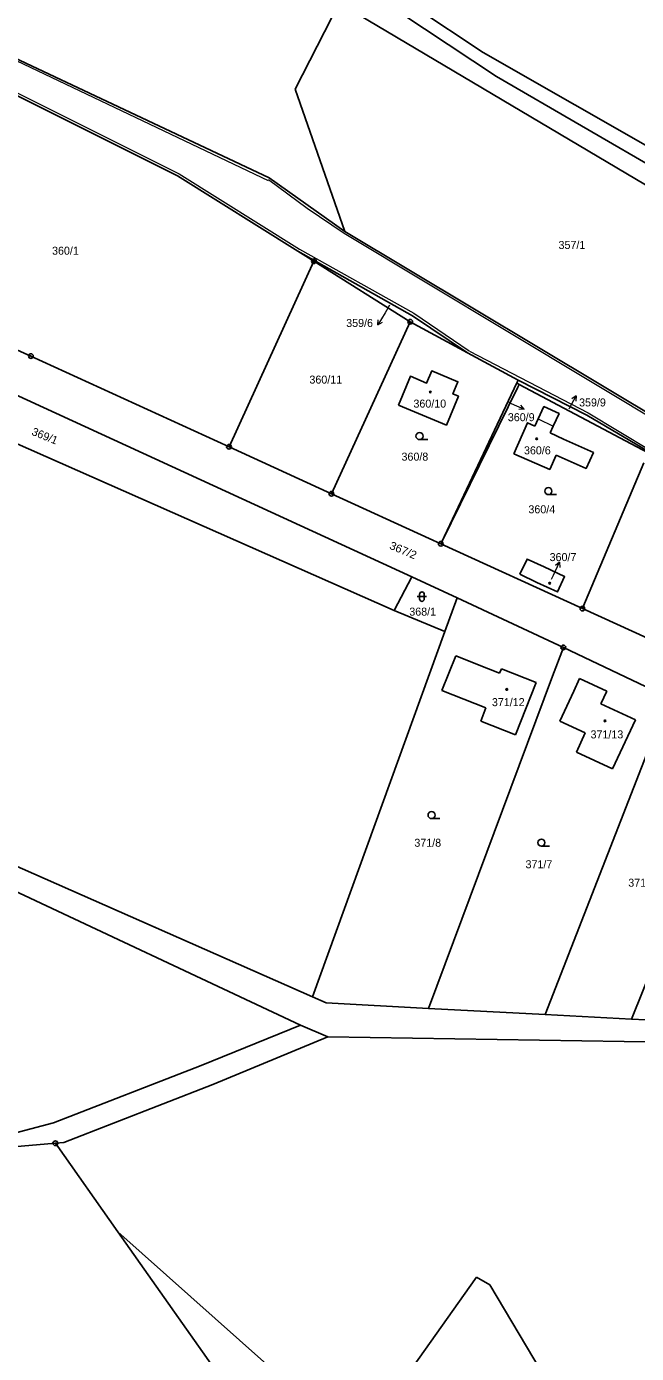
# Model space of a CAD drawing. Extents: x -633485 to -630509, y -1112692 to -1108818.
# Drawn here: x -632393.4 to -632263.7, y -1111932.7 to -1111650.8 of the extents above; entities that cross this region are included whole.
import ezdxf
from ezdxf.enums import TextEntityAlignment as Align

# ---------------------------------------------------------------- set-up
doc = ezdxf.new("R2010")
doc.units = 0
doc.header["$LTSCALE"] = 0.68
for name, color, linetype, lineweight in [('1', 7, 'Continuous', 25), ('3', 7, 'Continuous', 25), ('4', 7, 'Continuous', 13), ('5', 7, 'Continuous', 25), ('7', 7, 'Continuous', 13), ('8', 7, 'Continuous', 25)]:
    doc.layers.add(name, color=color, linetype=linetype, lineweight=lineweight)
doc.layers.add('2', color=7, linetype='Continuous')

msp = doc.modelspace()

# ---------------------------------------------------------------- linework, layer by layer
at = {"layer": '1'}
for p, q in [((-632321.48, -1111642.92), (-632293.52, -1111661.47)), ((-632336.28, -1111664.14), (-632326.93, -1111645.87)), ((-632326.93, -1111645.87), (-632261.86, -1111684.44)), ((-632310.86, -1111646.71), (-632296.31, -1111656.36)), ((-632401.29, -1111654.98), (-632341.82, -1111682.99)), ((-632296.31, -1111656.36), (-632257.3, -1111678.64)), ((-632403.76, -1111661.33), (-632361.26, -1111682.53)), ((-632336.28, -1111664.14), (-632325.73, -1111694.38)), ((-632293.52, -1111661.47), (-632245.01, -1111689.64)), ((-632475.12, -1111683.9), (-632392.43, -1111720.84)), ((-632361.26, -1111682.53), (-632335.74, -1111698.55)), ((-632341.82, -1111682.99), (-632325.73, -1111694.38)), ((-632325.73, -1111694.38), (-632220.93, -1111757.12)), ((-632483.69, -1111700.54), (-632315.26, -1111774.87)), ((-632350.34, -1111740.12), (-632332.3, -1111700.71)), ((-632335.74, -1111698.55), (-632311.37, -1111712.28)), ((-632335.74, -1111698.55), (-632332.3, -1111700.71)), ((-632332.3, -1111700.71), (-632311.84, -1111713.55)), ((-632328.57, -1111750.09), (-632311.84, -1111713.55)), ((-632311.84, -1111713.55), (-632299.65, -1111720.15)), ((-632311.37, -1111712.28), (-632299.65, -1111720.15)), ((-632299.65, -1111720.15), (-632288.91, -1111725.97)), ((-632392.43, -1111720.84), (-632350.34, -1111740.12)), ((-632289.18, -1111726.54), (-632288.91, -1111725.97)), ((-632288.91, -1111725.97), (-632274.31, -1111733.41)), ((-632395.9, -1111728.92), (-632311.46, -1111767.74)), ((-632305.21, -1111760.47), (-632289.18, -1111726.54)), ((-632305.21, -1111760.47), (-632288.94, -1111727.46)), ((-632289.18, -1111726.54), (-632288.65, -1111726.87)), ((-632288.94, -1111727.46), (-632288.65, -1111726.87)), ((-632288.65, -1111726.87), (-632261.27, -1111741.38)), ((-632284.65, -1111734.2), (-632285.36, -1111735.72)), ((-632274.31, -1111733.41), (-632261.17, -1111741.15)), ((-632282.12, -1111737.18), (-632281.44, -1111735.71)), ((-632279.22, -1111738.49), (-632282.12, -1111737.18)), ((-632350.34, -1111740.12), (-632328.57, -1111750.09)), ((-632275.15, -1111774.29), (-632262.16, -1111743.5)), ((-632328.57, -1111750.09), (-632307.83, -1111759.59)), ((-632307.83, -1111759.59), (-632305.34, -1111760.73)), ((-632305.34, -1111760.73), (-632305.21, -1111760.47)), ((-632305.34, -1111760.73), (-632275.23, -1111774.49)), ((-632315.26, -1111774.87), (-632311.46, -1111767.74)), ((-632311.46, -1111767.74), (-632301.87, -1111772.21)), ((-632284.91, -1111768.92), (-632288.53, -1111767.18)), ((-632304.46, -1111779.34), (-632301.87, -1111772.21)), ((-632301.87, -1111772.21), (-632279.29, -1111782.74)), ((-632315.26, -1111774.87), (-632304.46, -1111779.34)), ((-632275.23, -1111774.49), (-632275.15, -1111774.29)), ((-632275.23, -1111774.49), (-632252.52, -1111784.87)), ((-632332.59, -1111857), (-632304.46, -1111779.34)), ((-632305.08, -1111791.92), (-632302.14, -1111784.5)), ((-632302.14, -1111784.5), (-632295.17, -1111787.28)), ((-632281.56, -1111788.82), (-632279.29, -1111782.74)), ((-632279.29, -1111782.74), (-632256.84, -1111793.46)), ((-632295.17, -1111787.28), (-632292.84, -1111788.2)), ((-632292.84, -1111788.2), (-632292.44, -1111787.26)), ((-632292.44, -1111787.26), (-632285.03, -1111790.16)), ((-632307.96, -1111859.42), (-632281.56, -1111788.82)), ((-632289.48, -1111801.32), (-632285.03, -1111790.16)), ((-632277.09, -1111792.06), (-632275.83, -1111789.31)), ((-632275.83, -1111789.31), (-632270.06, -1111792.02)), ((-632305.08, -1111791.92), (-632298.1, -1111794.67)), ((-632280.05, -1111798.38), (-632277.09, -1111792.06)), ((-632271.3, -1111794.73), (-632270.06, -1111792.02)), ((-632298.1, -1111794.67), (-632295.79, -1111795.58)), ((-632296.85, -1111798.39), (-632295.79, -1111795.58)), ((-632271.3, -1111794.73), (-632263.98, -1111798.12)), ((-632296.85, -1111798.39), (-632289.48, -1111801.32)), ((-632283.16, -1111860.74), (-632258.76, -1111798.26)), ((-632280.05, -1111798.38), (-632274.62, -1111800.9)), ((-632268.82, -1111808.56), (-632263.98, -1111798.12)), ((-632276.51, -1111804.98), (-632274.62, -1111800.9)), ((-632276.51, -1111804.98), (-632268.82, -1111808.56)), ((-632264.78, -1111861.71), (-632242.18, -1111805.12)), ((-632407.97, -1111823.75), (-632332.59, -1111857)), ((-632409.47, -1111828.13), (-632335.16, -1111862.99)), ((-632332.59, -1111857), (-632329.72, -1111858.27)), ((-632329.72, -1111858.27), (-632307.96, -1111859.42)), ((-632307.96, -1111859.42), (-632283.16, -1111860.74)), ((-632283.16, -1111860.74), (-632264.78, -1111861.71)), ((-632356.26, -1111871.52), (-632335.16, -1111862.99)), ((-632335.16, -1111862.99), (-632329.36, -1111865.46)), ((-632264.78, -1111861.71), (-632261.78, -1111861.87)), ((-632353.81, -1111875.59), (-632329.36, -1111865.46)), ((-632329.36, -1111865.46), (-632244.47, -1111866.78)), ((-632387.64, -1111883.74), (-632356.26, -1111871.52)), ((-632385.42, -1111887.9), (-632353.81, -1111875.59)), ((-632490.92, -1111910.84), (-632387.64, -1111883.74)), ((-632399.48, -1111889.14), (-632387.25, -1111888.06)), ((-632373.97, -1111906.88), (-632301.86, -1112009.08)), ((-632373.97, -1111906.88), (-632321.63, -1111953.4)), ((-632316.23, -1111942.57), (-632297.75, -1111916.51)), ((-632297.75, -1111916.51), (-632294.94, -1111918.17)), ((-632294.94, -1111918.17), (-632280.07, -1111943.06))]:
    msp.add_line(p, q, dxfattribs=at)
msp.add_lwpolyline([(-632314.32, -1111731.25), (-632311.79, -1111725.15), (-632308.35, -1111726.57), (-632307.27, -1111723.99), (-632301.68, -1111726.3), (-632302.74, -1111728.9), (-632301.6, -1111729.37), (-632304.14, -1111735.5)], close=True, dxfattribs=at)
for points in [[(-632281.44, -1111735.71), (-632280.21, -1111733.07), (-632283.43, -1111731.57), (-632284.65, -1111734.2)], [(-632285.36, -1111735.72), (-632286.89, -1111735.03), (-632289.78, -1111741.59)], [(-632280.78, -1111741.88), (-632274.45, -1111744.73), (-632272.91, -1111741.34), (-632279.22, -1111738.49)], [(-632289.78, -1111741.59), (-632282.16, -1111744.92), (-632280.78, -1111741.88)], [(-632288.53, -1111767.18), (-632286.99, -1111763.97), (-632283.38, -1111765.63)], [(-632283.38, -1111765.63), (-632279.03, -1111767.68), (-632280.52, -1111770.96), (-632284.91, -1111768.92)], [(-632373.97, -1111906.88), (-632387.25, -1111888.06), (-632385.42, -1111887.9)]]:
    msp.add_lwpolyline(points, dxfattribs=at)
at = {"layer": '3'}
for p, q in [((-632309.853, -1111738.6), (-632308.103, -1111738.6)), ((-632282.463, -1111750.28), (-632280.713, -1111750.28)), ((-632310.341, -1111771.951), (-632308.339, -1111771.951)), ((-632309.841, -1111771.451), (-632309.841, -1111772.452)), ((-632308.839, -1111772.452), (-632308.839, -1111771.451)), ((-632307.293, -1111819.11), (-632305.543, -1111819.11)), ((-632283.953, -1111824.96), (-632282.203, -1111824.96))]:
    msp.add_line(p, q, dxfattribs=at)
for centre in [(-632309.8529, -1111737.8498), (-632282.4629, -1111749.5298), (-632307.2929, -1111818.3598), (-632283.9529, -1111824.2098)]:
    msp.add_circle(centre, 0.75, dxfattribs=at)
for centre, start, end in [((-632309.34, -1111771.4509), 0, 180), ((-632309.34, -1111772.4509), 180, 359.98789)]:
    msp.add_arc(centre, 0.5, start, end, dxfattribs=at)
at = {"layer": '4'}
msp.add_line((-632284.65, -1111734.2), (-632281.44, -1111735.71), dxfattribs=at)
for points in [[(-632913.37, -1111284.14), (-632903.43, -1111296.53), (-632901.68, -1111300.19), (-632898.25, -1111304.55), (-632839.91, -1111353.26), (-632811.33, -1111379.91), (-632794.53, -1111397.53), (-632770.8, -1111417.89), (-632733.49, -1111454.85), (-632690.42, -1111489.51), (-632643.95, -1111526.86), (-632609.47, -1111548.69), (-632587.98, -1111560.83), (-632517.06, -1111600.62), (-632481.03, -1111616.96), (-632456.42, -1111631), (-632403.52, -1111660.86), (-632360.95, -1111682.17), (-632335.39, -1111698.14), (-632311.04, -1111711.72), (-632299.3, -1111719.74)], [(-632341.95, -1111683.59), (-632401.36, -1111655.37), (-632476.91, -1111613.68), (-632582.67, -1111558.34), (-632600.05, -1111546.02), (-632611.42, -1111539.57), (-632654.27, -1111513.39), (-632683.89, -1111486.15), (-632729.95, -1111449.04), (-632752.07, -1111426.79), (-632756.78, -1111422.08), (-632808.8, -1111374.42), (-632836.64, -1111350.53)], [(-632121.32, -1111799.36), (-632153.88, -1111790.41), (-632209.17, -1111764.74), (-632221.14, -1111757.71), (-632325.85, -1111694.81), (-632333.76, -1111689.52), (-632341.95, -1111683.42)], [(-632299.24, -1111719.8), (-632274.04, -1111732.92), (-632260.85, -1111740.83), (-632218.48, -1111766.08), (-632218.07, -1111765.09), (-632212.08, -1111768.29), (-632212.31, -1111769.16), (-632189.88, -1111779.63)]]:
    msp.add_lwpolyline(points, dxfattribs=at)
at = {"layer": '5'}
for centre in [(-632307.5468, -1111728.4892), (-632284.9668, -1111738.4292), (-632282.1968, -1111769.0992), (-632291.3068, -1111791.6692), (-632270.4268, -1111798.3392)]:
    msp.add_circle(centre, 0.175, dxfattribs=at)
at = {"layer": '7'}
for p, q in [((-632318.68, -1111714.239), (-632317.746, -1111713.622)), ((-632287.64, -1111732.158), (-632288.336, -1111731.281)), ((-632276.555, -1111729.325), (-632277.479, -1111729.958)), ((-632280.074, -1111764.663), (-632280.964, -1111765.343))]:
    msp.add_line(p, q, dxfattribs=at)
for points in [[(-632316.24, -1111710), (-632317.18, -1111711.64), (-632318.68, -1111714.239), (-632318.613, -1111713.121)], [(-632290.85, -1111730.67), (-632290.36, -1111730.89), (-632287.64, -1111732.158), (-632288.759, -1111732.189)], [(-632278.07, -1111732.06), (-632278.01, -1111731.95), (-632276.555, -1111729.325), (-632276.603, -1111730.444)], [(-632281.82, -1111768.26), (-632281.39, -1111767.36), (-632280.074, -1111764.663), (-632280.063, -1111765.782)]]:
    msp.add_lwpolyline(points, dxfattribs=at)
at = {"layer": '8'}
for centre, radius in [((-632332.3, -1111700.7099), 0.5), ((-632332.3, -1111700.7099), 0.0303), ((-632311.84, -1111713.5499), 0.5), ((-632311.84, -1111713.5499), 0.0303), ((-632392.43, -1111720.8399), 0.5), ((-632392.43, -1111720.8399), 0.0303), ((-632350.34, -1111740.1199), 0.5), ((-632350.34, -1111740.1199), 0.0303), ((-632328.57, -1111750.0899), 0.5), ((-632328.57, -1111750.0899), 0.0303), ((-632305.34, -1111760.7299), 0.5), ((-632305.34, -1111760.7299), 0.0303), ((-632275.23, -1111774.4899), 0.5), ((-632275.23, -1111774.4899), 0.0303), ((-632279.29, -1111782.7399), 0.5), ((-632279.29, -1111782.7399), 0.0303), ((-632387.25, -1111888.0599), 0.5), ((-632387.25, -1111888.0599), 0.0303)]:
    msp.add_circle(centre, radius, dxfattribs=at)

# ---------------------------------------------------------------- texts
at = {"layer": '2'}
for s, p in [('360/1', (-632387.95, -1111699.315)), ('357/1', (-632280.31, -1111698.095)), ('360/11', (-632333.25, -1111726.695)), ('360/8', (-632313.68, -1111743.065)), ('360/4', (-632286.71, -1111754.245)), ('368/1', (-632312.03, -1111775.985)), ('371/12', (-632294.47, -1111795.215)), ('371/13', (-632273.51, -1111802.065)), ('371/8', (-632310.95, -1111825.085)), ('371/7', (-632287.32, -1111829.655)), ('371/6', (-632265.49, -1111833.575))]:
    msp.add_text(s, height=1.7, dxfattribs=at).set_placement(p)
for s, p in [('359/6', (-632322.59, -1111714.665)), ('360/10', (-632307.67, -1111731.795)), ('359/9', (-632273.1, -1111731.545)), ('360/9', (-632288.24, -1111734.685)), ('360/6', (-632284.81, -1111741.725)), ('360/7', (-632279.36, -1111764.405))]:
    msp.add_text(s, height=1.7, dxfattribs=at).set_placement(p, align=Align.CENTER)
msp.add_text('369/1', height=1.7, rotation=338, dxfattribs=at).set_placement((-632392.429, -1111737.534))
at = {"layer": '2', "width": 1.05}
msp.add_text('367/2', height=1.7, rotation=337, dxfattribs=at).set_placement((-632316.406, -1111761.721))

doc.saveas('drawing.dxf')
